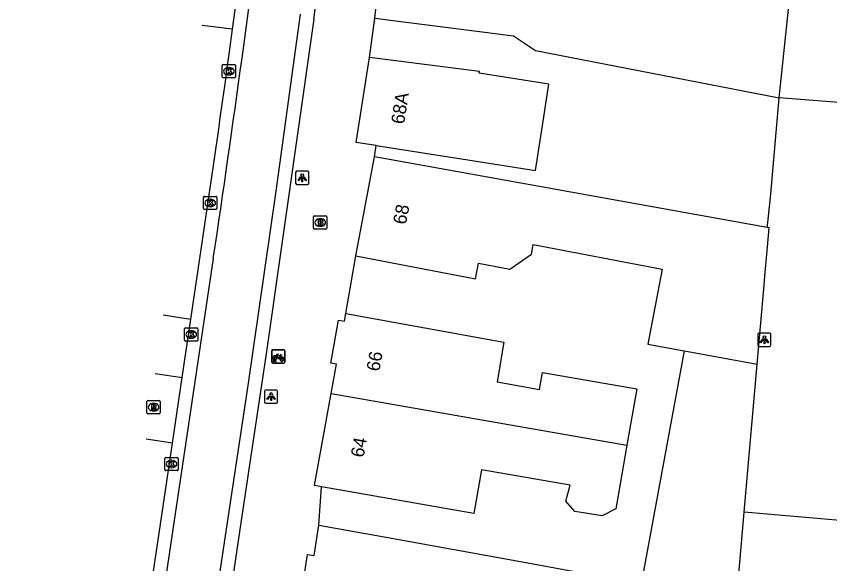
# Model space of a CAD drawing. Extents: x 160861 to 161308, y 384024 to 384878.
# Drawn here: x 161106.7 to 161168.1, y 384129.3 to 384170.6 of the extents above; entities that cross this region are included whole.
import ezdxf

# ---------------------------------------------------------------- set-up
doc = ezdxf.new("R2010")
doc.units = 0
for name, color, linetype in [('IMGEO_Brandkraan', 7, 'Continuous'), ('IMGEO_Fietsenrek', 7, 'Continuous'), ('IMGEO_Fietspad_gesloten', 7, 'Continuous'), ('IMGEO_Fietspad_open', 7, 'Continuous'), ('IMGEO_Kolk', 7, 'Continuous'), ('IMGEO_Lichtpunt', 7, 'Continuous'), ('IMGEO_Pand', 7, 'Continuous'), ('IMGEO_Pand_nummerreeks', 7, 'Continuous'), ('IMGEO_Rijbaan_lokaal_open', 7, 'Continuous'), ('IMGEO_Rioolput', 7, 'Continuous'), ('IMGEO_Voetpad_open', 7, 'Continuous')]:
    doc.layers.add(name, color=color, linetype=linetype)

msp = doc.modelspace()

# ---------------------------------------------------------------- linework, layer by layer
at = {"layer": 'IMGEO_Brandkraan'}
for p, q in [((161129.144, 384154.645), (161129.144, 384155.497)), ((161129.219, 384155.571), (161130.071, 384155.571)), ((161129.632, 384155.351), (161129.657, 384155.351)), ((161130.145, 384155.497), (161130.145, 384154.645)), ((161129.655, 384154.791), (161129.63, 384154.791)), ((161130.071, 384154.571), (161129.219, 384154.571))]:
    msp.add_line(p, q, dxfattribs=at)
for points in [[(161129.144, 384154.645), (161129.144, 384155.497)], [(161129.219, 384155.571), (161130.071, 384155.571)], [(161130.145, 384155.497), (161130.145, 384154.645)], [(161129.492, 384155.271), (161129.492, 384154.871), (161129.705, 384154.871)], [(161129.723, 384155.271), (161129.492, 384155.271)], [(161129.671, 384155.19), (161129.617, 384155.19), (161129.617, 384155.114)], [(161129.617, 384155.114), (161129.67, 384155.114)], [(161129.679, 384155.038), (161129.617, 384155.038), (161129.617, 384154.957)], [(161129.617, 384154.957), (161129.679, 384154.957)], [(161130.071, 384154.571), (161129.219, 384154.571)]]:
    msp.add_lwpolyline(points, dxfattribs=at)
for centre, radius, start, end in [((161129.221, 384155.495), 0.0765, 91.55205, 178.44795), ((161129.221, 384155.495), 0.0765, 91.55205, 178.44795), ((161130.069, 384155.495), 0.0765, 1.55205, 88.44795), ((161130.069, 384155.495), 0.0765, 1.55205, 88.44795), ((161129.672, 384155.152), 0.0379, 267.82845, 90.93552), ((161129.68, 384154.997), 0.0404, 269.87594, 90.50774), ((161129.711, 384155.122), 0.251, 268.66757, 293.53466), ((161129.727, 384155.126), 0.145, 59.4692, 91.53667), ((161129.752, 384155.173), 0.0922, 285.51372, 58.15012), ((161129.757, 384154.981), 0.105, 301.31148, 78.98903), ((161129.221, 384154.647), 0.0765, 181.55205, 268.44795), ((161129.221, 384154.647), 0.0765, 181.55205, 268.44795), ((161130.069, 384154.647), 0.0765, 271.55205, 358.44795), ((161130.069, 384154.647), 0.0765, 271.55205, 358.44795)]:
    msp.add_arc(centre, radius, start, end, dxfattribs=at)
for centre, major_axis, ratio, start_param, end_param in [((161129.631, 384155.071), (-0.387, 0.002), 0.722429, 4.712389, 7.853982), ((161129.656, 384155.071), (-0.39, 0.002), 0.717154, 1.570796, 4.712389)]:
    msp.add_ellipse(centre, major_axis=major_axis, ratio=ratio, start_param=start_param, end_param=end_param, dxfattribs=at)
at = {"layer": 'IMGEO_Fietsenrek'}
for p, q in [((161126.05, 384145.47), (161126.891, 384145.47)), ((161126.891, 384145.47), (161126.05, 384145.47)), ((161125.975, 384144.545), (161125.975, 384145.386)), ((161125.975, 384145.386), (161125.975, 384144.545)), ((161126.662, 384145.019), (161126.698, 384144.924)), ((161126.975, 384145.395), (161126.975, 384144.554)), ((161126.975, 384144.554), (161126.975, 384145.395)), ((161126.9, 384144.47), (161126.059, 384144.47)), ((161126.059, 384144.47), (161126.9, 384144.47)), ((161126.102, 384144.554), (161126.141, 384144.714)), ((161126.136, 384144.554), (161126.102, 384144.554)), ((161126.171, 384144.702), (161126.136, 384144.554)), ((161126.213, 384144.726), (161126.212, 384144.73)), ((161126.254, 384144.554), (161126.22, 384144.696)), ((161126.244, 384144.737), (161126.245, 384144.73)), ((161126.252, 384144.7), (161126.287, 384144.554)), ((161126.287, 384144.554), (161126.254, 384144.554))]:
    msp.add_line(p, q, dxfattribs=at)
for points in [[(161126.309, 384144.944), (161126.257, 384144.854), (161126.217, 384144.829), (161126.218, 384144.876), (161126.273, 384144.97)], [(161126.288, 384144.996), (161126.383, 384145.16), (161126.469, 384145.146), (161126.471, 384145.137), (161126.415, 384145.126), (161126.388, 384145.081), (161126.644, 384145.04)], [(161126.584, 384144.752), (161126.534, 384144.752), (161126.343, 384145.003), (161126.324, 384144.971)], [(161126.631, 384145.015), (161126.374, 384145.056), (161126.357, 384145.027), (161126.524, 384144.807), (161126.631, 384145.015)], [(161126.679, 384144.917), (161126.649, 384144.994), (161126.54, 384144.776), (161126.583, 384144.776)], [(161126.613, 384144.776), (161126.733, 384144.775), (161126.689, 384144.889)], [(161126.709, 384144.896), (161126.764, 384144.751), (161126.614, 384144.751)], [(161126.644, 384145.04), (161126.669, 384145.089), (161126.663, 384145.093), (161126.64, 384145.097), (161126.628, 384145.104), (161126.627, 384145.107), (161126.629, 384145.112), (161126.724, 384145.097), (161126.726, 384145.087), (161126.716, 384145.074), (161126.704, 384145.068), (161126.69, 384145.074), (161126.662, 384145.019)]]:
    msp.add_lwpolyline(points, dxfattribs=at)
for centre, radius, start, end in [((161126.053, 384145.392), 0.0779, 92.4484, 184.28452), ((161126.053, 384145.392), 0.0779, 92.4484, 184.28452), ((161126.897, 384145.392), 0.0779, 2.4484, 94.28452), ((161126.897, 384145.392), 0.0779, 2.4484, 94.28452), ((161126.215, 384144.855), 0.159, 62.67661, 242.13685), ((161126.215, 384144.855), 0.129, 63.31916, 238.90302), ((161126.215, 384144.855), 0.129, 283.60429, 43.43025), ((161126.215, 384144.855), 0.159, 283.5766, 46.60424), ((161126.742, 384144.771), 0.159, 113.3408, 178.32165), ((161126.742, 384144.771), 0.159, 187.0065, 105.77075), ((161126.742, 384144.771), 0.129, 113.92302, 177.95563), ((161126.742, 384144.771), 0.129, 188.67146, 104.58832), ((161126.053, 384144.548), 0.0779, 182.4484, 274.28452), ((161126.053, 384144.548), 0.0779, 182.4484, 274.28452), ((161126.195, 384144.726), 0.0499, 12.8025, 158.69338), ((161126.215, 384144.855), 0.159, 253.99666, 271.78671), ((161126.195, 384144.726), 0.0174, 12.8025, 163.45023), ((161126.215, 384144.855), 0.129, 253.41502, 269.02044), ((161126.897, 384144.548), 0.0779, 272.4484, 4.28452), ((161126.897, 384144.548), 0.0779, 272.4484, 4.28452)]:
    msp.add_arc(centre, radius, start, end, dxfattribs=at)
at = {"layer": 'IMGEO_Fietspad_gesloten'}
for points in [[(161110.393, 384047.415), (161109.564, 384047.564), (161116.482, 384091.339), (161122.797, 384133.458), (161124.195, 384142.785), (161126.322, 384157.442), (161128.16, 384170.784)], [(161121.567, 384152.354), (161112.414, 384091.035), (161106.696, 384054.799)]]:
    msp.add_lwpolyline(points, dxfattribs=at)
msp.add_arc((159944.784, 384329.021), 1189.97, 351.462123, 352.931795, dxfattribs=at)
at = {"layer": 'IMGEO_Fietspad_open'}
for points in [[(161123.022, 384169.656), (161123.322, 384171.881), (161123.535, 384173.486)], [(161129.156, 384170.412), (161125.557, 384145.161), (161123.782, 384133.28), (161122.357, 384123.74), (161117.44, 384091.02), (161112.803, 384061.669), (161110.455, 384047.735), (161110.393, 384047.415)], [(161122.787, 384167.937), (161123.022, 384169.656)], [(161119.864, 384147.777), (161120.417, 384151.506)], [(161119.212, 384143.381), (161119.588, 384145.918), (161119.864, 384147.777)], [(161118.477, 384138.424), (161119.212, 384143.381)], [(161116.844, 384127.41), (161117.471, 384131.639), (161118.477, 384138.424)]]:
    msp.add_lwpolyline(points, dxfattribs=at)
for centre, radius, start, end in [((159749.61, 384354.589), 1391.786, 352.395662, 353.589555), ((160008.479, 384320.278), 1124.673, 351.369422, 352.21516)]:
    msp.add_arc(centre, radius, start, end, dxfattribs=at)
at = {"layer": 'IMGEO_Kolk'}
for p, q in [((161122.32, 384166.982), (161123.172, 384166.982)), ((161122.245, 384166.056), (161122.245, 384166.908)), ((161122.733, 384166.762), (161122.758, 384166.762)), ((161123.246, 384166.908), (161123.246, 384166.056)), ((161123.172, 384165.982), (161122.32, 384165.982)), ((161122.756, 384166.202), (161122.731, 384166.202)), ((161120.836, 384156.119), (161120.836, 384156.971)), ((161120.911, 384157.045), (161121.763, 384157.045)), ((161121.324, 384156.825), (161121.349, 384156.825)), ((161121.837, 384156.971), (161121.837, 384156.119)), ((161121.763, 384156.045), (161120.911, 384156.045)), ((161121.347, 384156.265), (161121.322, 384156.265)), ((161119.4, 384146.203), (161119.4, 384147.055)), ((161119.475, 384147.129), (161120.327, 384147.129)), ((161119.888, 384146.909), (161119.913, 384146.909)), ((161120.401, 384147.055), (161120.401, 384146.203)), ((161120.327, 384146.129), (161119.475, 384146.129)), ((161119.911, 384146.349), (161119.886, 384146.349)), ((161117.915, 384136.428), (161117.915, 384137.28)), ((161117.99, 384137.354), (161118.842, 384137.354)), ((161118.403, 384137.134), (161118.428, 384137.134)), ((161118.916, 384137.28), (161118.916, 384136.428)), ((161118.842, 384136.354), (161117.99, 384136.354)), ((161118.426, 384136.574), (161118.401, 384136.574))]:
    msp.add_line(p, q, dxfattribs=at)
for points in [[(161122.32, 384166.982), (161123.172, 384166.982)], [(161122.245, 384166.056), (161122.245, 384166.908)], [(161122.566, 384166.682), (161122.689, 384166.682), (161122.689, 384166.531), (161122.819, 384166.682), (161122.983, 384166.682), (161122.837, 384166.531), (161122.99, 384166.282), (161122.838, 384166.282), (161122.753, 384166.446), (161122.689, 384166.379), (161122.689, 384166.282), (161122.566, 384166.282), (161122.566, 384166.682)], [(161123.246, 384166.908), (161123.246, 384166.056)], [(161123.172, 384165.982), (161122.32, 384165.982)], [(161120.836, 384156.119), (161120.836, 384156.971)], [(161120.911, 384157.045), (161121.763, 384157.045)], [(161121.157, 384156.745), (161121.28, 384156.745), (161121.28, 384156.594), (161121.41, 384156.745), (161121.574, 384156.745), (161121.428, 384156.594), (161121.581, 384156.345), (161121.429, 384156.345), (161121.344, 384156.509), (161121.28, 384156.442), (161121.28, 384156.345), (161121.157, 384156.345), (161121.157, 384156.745)], [(161121.837, 384156.971), (161121.837, 384156.119)], [(161121.763, 384156.045), (161120.911, 384156.045)], [(161119.4, 384146.203), (161119.4, 384147.055)], [(161119.475, 384147.129), (161120.327, 384147.129)], [(161119.721, 384146.829), (161119.844, 384146.829), (161119.844, 384146.678), (161119.974, 384146.829), (161120.138, 384146.829), (161119.992, 384146.678), (161120.145, 384146.429), (161119.993, 384146.429), (161119.908, 384146.593), (161119.844, 384146.526), (161119.844, 384146.429), (161119.721, 384146.429), (161119.721, 384146.829)], [(161120.401, 384147.055), (161120.401, 384146.203)], [(161120.327, 384146.129), (161119.475, 384146.129)], [(161117.915, 384136.428), (161117.915, 384137.28)], [(161117.99, 384137.354), (161118.842, 384137.354)], [(161118.236, 384137.054), (161118.359, 384137.054), (161118.359, 384136.903), (161118.489, 384137.054), (161118.653, 384137.054), (161118.507, 384136.903), (161118.66, 384136.654), (161118.508, 384136.654), (161118.423, 384136.818), (161118.359, 384136.751), (161118.359, 384136.654), (161118.236, 384136.654), (161118.236, 384137.054)], [(161118.916, 384137.28), (161118.916, 384136.428)], [(161118.842, 384136.354), (161117.99, 384136.354)]]:
    msp.add_lwpolyline(points, dxfattribs=at)
for centre, start, end in [((161122.322, 384166.906), 91.55205, 178.44795), ((161122.322, 384166.906), 91.55205, 178.44795), ((161123.17, 384166.906), 1.55205, 88.44795), ((161123.17, 384166.906), 1.55205, 88.44795), ((161122.322, 384166.058), 181.55205, 268.44795), ((161122.322, 384166.058), 181.55205, 268.44795), ((161123.17, 384166.058), 271.55205, 358.44795), ((161123.17, 384166.058), 271.55205, 358.44795), ((161120.913, 384156.969), 91.55205, 178.44795), ((161120.913, 384156.969), 91.55205, 178.44795), ((161121.761, 384156.969), 1.55205, 88.44795), ((161121.761, 384156.969), 1.55205, 88.44795), ((161120.913, 384156.121), 181.55205, 268.44795), ((161120.913, 384156.121), 181.55205, 268.44795), ((161121.761, 384156.121), 271.55205, 358.44795), ((161121.761, 384156.121), 271.55205, 358.44795), ((161119.477, 384147.053), 91.55205, 178.44795), ((161119.477, 384147.053), 91.55205, 178.44795), ((161120.325, 384147.053), 1.55205, 88.44795), ((161120.325, 384147.053), 1.55205, 88.44795), ((161119.477, 384146.205), 181.55205, 268.44795), ((161119.477, 384146.205), 181.55205, 268.44795), ((161120.325, 384146.205), 271.55205, 358.44795), ((161120.325, 384146.205), 271.55205, 358.44795), ((161117.992, 384137.278), 91.55205, 178.44795), ((161117.992, 384137.278), 91.55205, 178.44795), ((161118.84, 384137.278), 1.55205, 88.44795), ((161118.84, 384137.278), 1.55205, 88.44795), ((161117.992, 384136.43), 181.55205, 268.44795), ((161117.992, 384136.43), 181.55205, 268.44795), ((161118.84, 384136.43), 271.55205, 358.44795), ((161118.84, 384136.43), 271.55205, 358.44795)]:
    msp.add_arc(centre, 0.0765, start, end, dxfattribs=at)
for centre, major_axis, ratio, start_param, end_param in [((161122.732, 384166.482), (-0.387, 0.002), 0.722429, 4.712389, 7.853982), ((161122.757, 384166.482), (-0.39, 0.002), 0.717154, 1.570796, 4.712389), ((161121.323, 384156.545), (-0.387, 0.002), 0.722429, 4.712389, 7.853982), ((161121.348, 384156.545), (-0.39, 0.002), 0.717154, 1.570796, 4.712389), ((161119.887, 384146.629), (-0.387, 0.002), 0.722429, 4.712389, 7.853982), ((161119.912, 384146.629), (-0.39, 0.002), 0.717154, 1.570796, 4.712389), ((161118.402, 384136.854), (-0.387, 0.002), 0.722429, 4.712389, 7.853982), ((161118.427, 384136.854), (-0.39, 0.002), 0.717154, 1.570796, 4.712389)]:
    msp.add_ellipse(centre, major_axis=major_axis, ratio=ratio, start_param=start_param, end_param=end_param, dxfattribs=at)
at = {"layer": 'IMGEO_Lichtpunt'}
for p, q in [((161127.786, 384158.847), (161127.786, 384158.04)), ((161127.786, 384158.847), (161127.786, 384158.04)), ((161128.688, 384158.942), (161127.88, 384158.942)), ((161128.688, 384158.942), (161127.88, 384158.942)), ((161128.782, 384158.04), (161128.782, 384158.847)), ((161128.782, 384158.04), (161128.782, 384158.847)), ((161127.88, 384157.946), (161128.688, 384157.946)), ((161127.88, 384157.946), (161128.688, 384157.946)), ((161163.569, 384146.726), (161162.761, 384146.726)), ((161163.569, 384146.726), (161162.761, 384146.726)), ((161162.667, 384146.631), (161162.667, 384145.824)), ((161162.667, 384146.631), (161162.667, 384145.824)), ((161163.663, 384145.824), (161163.663, 384146.631)), ((161163.663, 384145.824), (161163.663, 384146.631)), ((161162.761, 384145.73), (161163.569, 384145.73)), ((161162.761, 384145.73), (161163.569, 384145.73)), ((161126.332, 384142.437), (161125.524, 384142.437)), ((161126.332, 384142.437), (161125.524, 384142.437)), ((161125.43, 384142.342), (161125.43, 384141.535)), ((161125.43, 384142.342), (161125.43, 384141.535)), ((161126.426, 384141.535), (161126.426, 384142.342)), ((161126.426, 384141.535), (161126.426, 384142.342)), ((161125.524, 384141.441), (161126.332, 384141.441)), ((161125.524, 384141.441), (161126.332, 384141.441))]:
    msp.add_line(p, q, dxfattribs=at)
for points in [[(161128.16, 384158.511), (161128.199, 384158.483), (161128.011, 384158.221), (161127.973, 384158.248), (161128.16, 384158.511)], [(161128.262, 384158.463), (161128.309, 384158.463), (161128.309, 384158.141), (161128.262, 384158.141), (161128.262, 384158.463)], [(161128.372, 384158.483), (161128.41, 384158.51), (161128.597, 384158.248), (161128.558, 384158.22), (161128.372, 384158.483)], [(161163.041, 384146.295), (161163.08, 384146.267), (161162.892, 384146.005), (161162.854, 384146.032), (161163.041, 384146.295)], [(161163.143, 384146.247), (161163.19, 384146.247), (161163.19, 384145.925), (161163.143, 384145.925), (161163.143, 384146.247)], [(161163.253, 384146.267), (161163.291, 384146.294), (161163.478, 384146.032), (161163.439, 384146.004), (161163.253, 384146.267)], [(161125.804, 384142.006), (161125.843, 384141.978), (161125.655, 384141.716), (161125.617, 384141.743), (161125.804, 384142.006)], [(161125.906, 384141.958), (161125.953, 384141.958), (161125.953, 384141.636), (161125.906, 384141.636), (161125.906, 384141.958)], [(161126.016, 384141.978), (161126.054, 384142.005), (161126.241, 384141.743), (161126.202, 384141.715), (161126.016, 384141.978)]]:
    msp.add_lwpolyline(points, dxfattribs=at)
for centre in [(161128.285, 384158.645), (161163.166, 384146.429), (161125.929, 384142.14)]:
    msp.add_circle(centre, 0.0994, dxfattribs=at)
for centre, start, end in [((161127.88, 384158.847), 90, 180), ((161127.88, 384158.847), 90, 180), ((161128.688, 384158.847), 0, 90), ((161128.688, 384158.847), 0, 90), ((161127.88, 384158.04), 180, 270), ((161127.88, 384158.04), 180, 270), ((161128.688, 384158.04), 270, 0), ((161128.688, 384158.04), 270, 360), ((161162.761, 384146.631), 90, 180), ((161162.761, 384146.631), 90, 180), ((161163.569, 384146.631), 0, 90), ((161163.569, 384146.631), 0, 90), ((161162.761, 384145.824), 180, 270), ((161162.761, 384145.824), 180, 270), ((161163.569, 384145.824), 270, 0), ((161163.569, 384145.824), 270, 360), ((161125.524, 384142.342), 90, 180), ((161125.524, 384142.342), 90, 180), ((161126.332, 384142.342), 0, 90), ((161126.332, 384142.342), 0, 90), ((161125.524, 384141.535), 180, 270), ((161125.524, 384141.535), 180, 270), ((161126.332, 384141.535), 270, 0), ((161126.332, 384141.535), 270, 360)]:
    msp.add_arc(centre, 0.0946, start, end, dxfattribs=at)
at = {"layer": 'IMGEO_Pand'}
for points in [[(161133.76, 384170.475), (161133.817, 384170.951), (161135.131, 384181.891), (161135.206, 384182.519)], [(161164.271, 384164.475), (161165.191, 384173.102), (161162.893, 384173.404), (161163.034, 384174.574), (161163.584, 384179.139)], [(161133.76, 384170.475), (161144.241, 384169.164), (161145.898, 384168.047), (161164.271, 384164.475)], [(161133.865, 384160.877), (161132.354, 384161.115), (161133.363, 384167.531)], [(161133.865, 384160.877), (161140.786, 384159.789), (161145.88, 384158.988), (161146.363, 384162.064), (161146.903, 384165.5), (161141.638, 384166.329), (161141.66, 384166.465), (161133.363, 384167.531)], [(161132.323, 384152.557), (161133.749, 384160.034)], [(161163.375, 384154.705), (161133.749, 384160.034)], [(161162.62, 384144.394), (161163.115, 384150.069), (161163.197, 384151.012), (161163.398, 384153.237), (161163.528, 384154.677), (161163.375, 384154.705)], [(161132.323, 384152.557), (161141.361, 384150.833), (161141.586, 384152.012), (161143.943, 384151.562), (161145.582, 384152.676), (161145.72, 384153.403), (161155.447, 384151.548), (161154.367, 384145.888), (161157.102, 384145.393), (161157.131, 384145.388)], [(161130.469, 384142.176), (161130.871, 384144.378), (161130.429, 384144.459), (161131.021, 384147.705), (161131.463, 384147.624), (161131.57, 384148.214)], [(161131.57, 384148.214), (161143.508, 384146.037), (161142.984, 384143.043), (161146.193, 384142.482), (161146.417, 384143.765), (161153.536, 384142.52), (161152.793, 384138.276)], [(161153.888, 384127.815), (161157.131, 384145.388)], [(161157.131, 384145.388), (161162.62, 384144.394)], [(161161.646, 384133.216), (161162.62, 384144.394)], [(161129.735, 384135.13), (161129.2, 384135.224), (161130.469, 384142.176)], [(161130.469, 384142.176), (161152.793, 384138.276)], [(161152.793, 384138.276), (161152.153, 384134.621), (161151.951, 384133.468), (161150.912, 384132.932), (161148.848, 384133.281), (161148.183, 384134.058), (161148.495, 384135.261), (161141.825, 384136.427), (161141.246, 384133.118), (161129.735, 384135.13)], [(161161.061, 384126.511), (161161.646, 384133.216)], [(161127.497, 384122.367), (161128.671, 384130.021), (161129.19, 384129.941), (161129.542, 384132.24)], [(161129.542, 384132.24), (161134.463, 384131.354), (161144.758, 384129.5), (161153.888, 384127.815)]]:
    msp.add_lwpolyline(points, dxfattribs=at)
at = {"layer": 'IMGEO_Rijbaan_lokaal_open'}
for points in [[(161163.375, 384154.705), (161163.415, 384155.077), (161163.642, 384157.219), (161164.271, 384164.475)], [(161171.684, 384163.91), (161164.271, 384164.475)], [(161169.161, 384132.561), (161161.646, 384133.216)]]:
    msp.add_lwpolyline(points, dxfattribs=at)
at = {"layer": 'IMGEO_Rioolput'}
for p, q in [((161116.563, 384140.717), (161116.563, 384141.569)), ((161116.638, 384141.643), (161117.49, 384141.643)), ((161117.051, 384141.423), (161117.076, 384141.423)), ((161117.564, 384141.569), (161117.564, 384140.717)), ((161117.49, 384140.643), (161116.638, 384140.643)), ((161117.074, 384140.863), (161117.049, 384140.863))]:
    msp.add_line(p, q, dxfattribs=at)
for points in [[(161116.563, 384140.717), (161116.563, 384141.569)], [(161116.638, 384141.643), (161117.49, 384141.643)], [(161117.152, 384141.341), (161116.9, 384141.343), (161116.9, 384140.943)], [(161117.078, 384141.262), (161117.024, 384141.262), (161117.024, 384141.181)], [(161117.024, 384141.181), (161117.076, 384141.181)], [(161117.564, 384141.569), (161117.564, 384140.717)], [(161117.49, 384140.643), (161116.638, 384140.643)], [(161116.9, 384140.943), (161117.024, 384140.943), (161117.024, 384141.105), (161117.035, 384141.105)], [(161117.082, 384141.076), (161117.153, 384140.943), (161117.293, 384140.943), (161117.228, 384141.069)]]:
    msp.add_lwpolyline(points, dxfattribs=at)
for centre, radius, start, end in [((161116.64, 384141.567), 0.0765, 91.55205, 178.44795), ((161116.64, 384141.567), 0.0765, 91.55205, 178.44795), ((161117.06, 384141.37), 0.19, 274.7715, 282.96867), ((161117.084, 384141.166), 0.0964, 77.00612, 93.18647), ((161117.098, 384141.223), 0.0378, 276.66336, 79.67722), ((161117.151, 384141.231), 0.109, 350.36119, 89.41601), ((161117.149, 384141.231), 0.112, 277.58423, 350.98172), ((161117.488, 384141.567), 0.0765, 1.55205, 88.44795), ((161117.488, 384141.567), 0.0765, 1.55205, 88.44795), ((161116.64, 384140.719), 0.0765, 181.55205, 268.44795), ((161116.64, 384140.719), 0.0765, 181.55205, 268.44795), ((161117.034, 384141.052), 0.0533, 26.02933, 88.69889), ((161117.133, 384141.016), 0.108, 29.51342, 73.79051), ((161117.488, 384140.719), 0.0765, 271.55205, 358.44795), ((161117.488, 384140.719), 0.0765, 271.55205, 358.44795)]:
    msp.add_arc(centre, radius, start, end, dxfattribs=at)
for centre, major_axis, ratio, start_param, end_param in [((161117.05, 384141.143), (-0.387, 0.002), 0.722429, 4.712389, 7.853982), ((161117.075, 384141.143), (-0.39, 0.002), 0.717154, 1.570796, 4.712389)]:
    msp.add_ellipse(centre, major_axis=major_axis, ratio=ratio, start_param=start_param, end_param=end_param, dxfattribs=at)
at = {"layer": 'IMGEO_Voetpad_open'}
for points in [[(161133.363, 384167.531), (161133.76, 384170.475)], [(161123.022, 384169.656), (161120.728, 384169.943)], [(161133.749, 384160.034), (161133.865, 384160.877)], [(161131.57, 384148.214), (161132.323, 384152.557)], [(161117.774, 384148.113), (161119.864, 384147.777)], [(161117.175, 384143.683), (161119.212, 384143.381)], [(161118.477, 384138.424), (161116.503, 384138.717)], [(161129.542, 384132.24), (161129.735, 384135.13)]]:
    msp.add_lwpolyline(points, dxfattribs=at)

# ---------------------------------------------------------------- texts
at = {"layer": 'IMGEO_Pand_nummerreeks'}
for s, rotation, p in [('68A', 81.10218, (161135.966, 384162.449)), ('68', 79.19996, (161136.104, 384154.872)), ('66', 79.65675, (161134.097, 384143.793)), ('64', 79.66405, (161132.912, 384137.299))]:
    msp.add_text(s, height=1, rotation=rotation, dxfattribs=at).set_placement(p)

doc.saveas('drawing.dxf')
